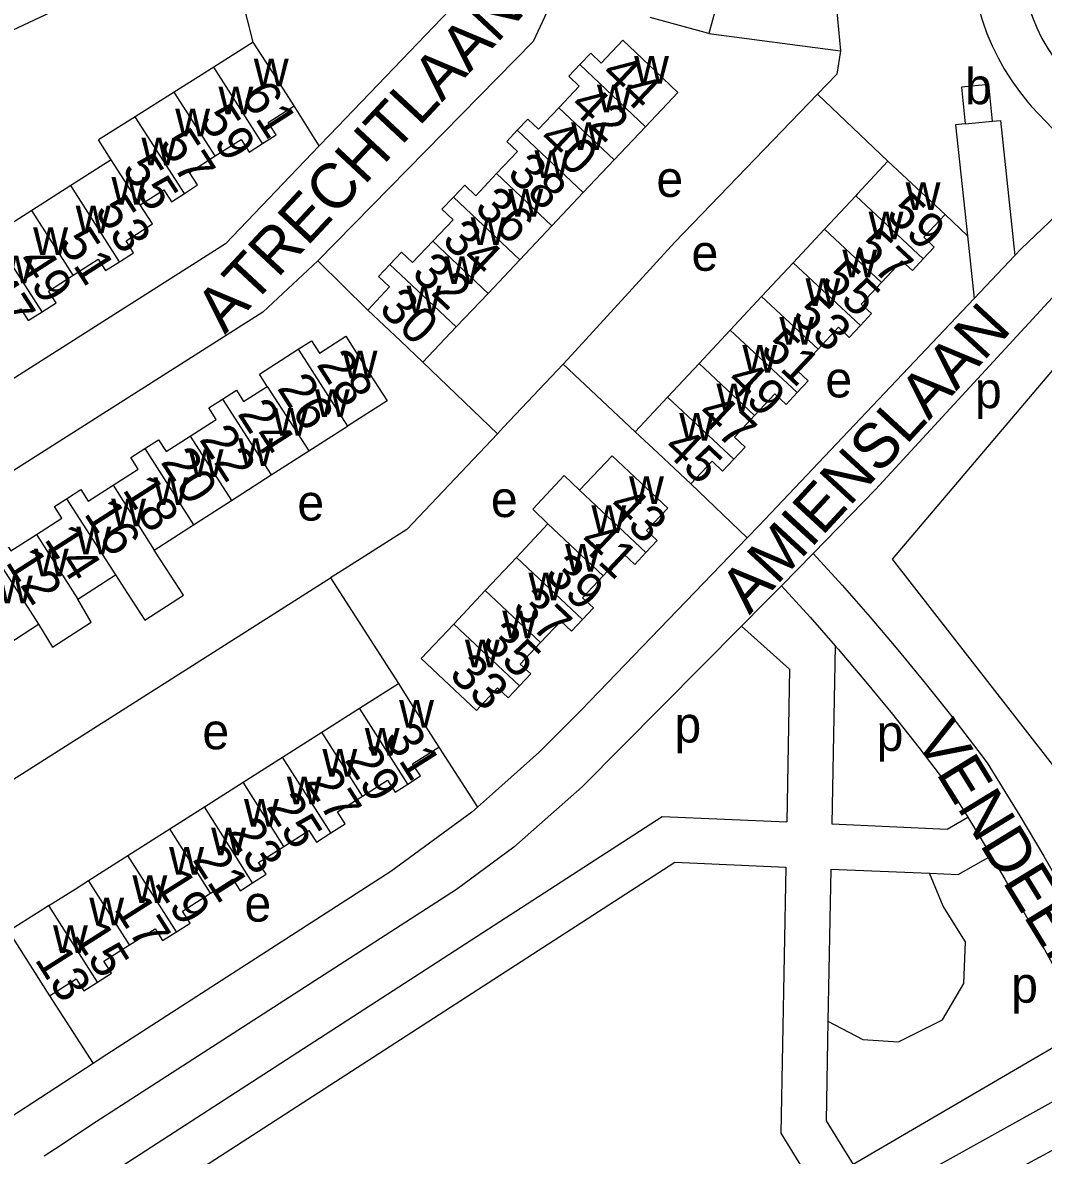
# Model space of a CAD drawing. Extents: x 157768 to 159790, y 387230 to 389604.
# Drawn here: x 159238.2 to 159351.4, y 389220.4 to 389346.2 of the extents above; entities that cross this region are included whole.
import ezdxf

# ---------------------------------------------------------------- set-up
doc = ezdxf.new("R2010")
doc.units = 0
for name, color, linetype in [('BLT_Basislijn', 7, 'Continuous'), ('BLT_Bebouwing', 7, 'Continuous'), ('BLT_Centroide', 7, 'Continuous'), ('BLT_Huisnummer', 7, 'Continuous'), ('BLT_Huisnummer_ tussenligend', 7, 'Continuous'), ('BLT_Onderverdeling_panden', 7, 'Continuous'), ('BLT_Straatnaam', 7, 'Continuous')]:
    doc.layers.add(name, color=color, linetype=linetype)

msp = doc.modelspace()

# ---------------------------------------------------------------- linework, layer by layer
at = {"layer": 'BLT_Basislijn'}
for p, q in [((159324.37, 389390.31), (159328.92, 389343.05)), ((159263.75, 389344), (159260.62, 389356.43)), ((159328.92, 389343.05), (159328.52, 389340.46)), ((159326.36, 389338.22), (159328.52, 389340.46)), ((159326.36, 389338.22), (159334.18, 389330.79)), ((159271.07, 389332.51), (159268.28, 389336.94)), ((159353.27, 389333.52), (159350.08, 389336.91)), ((159340.51, 389324.88), (159343.01, 389322.5)), ((159353.66, 389325.54), (159348.95, 389321.05)), ((159343.01, 389322.5), (159343.75, 389315.56)), ((159348.95, 389321.05), (159348.27, 389320.33)), ((159348.27, 389320.33), (159343.75, 389315.56)), ((159276.46, 389314.27), (159270.91, 389319.73)), ((159290.84, 389300.54), (159282.58, 389308.48)), ((159306.13, 389300.75), (159298.12, 389308.27)), ((159312.32, 389294.97), (159318.54, 389288.97)), ((159322.38, 389283.67), (159325.88, 389287.25)), ((159272.33, 389284.53), (159279.85, 389272.8)), ((159322.19, 389283.48), (159320.49, 389281.77)), ((159322.19, 389283.48), (159322.38, 389283.67)), ((159320.49, 389281.77), (159317.93, 389279.18)), ((159328.33, 389277.01), (159327.95, 389257.23)), ((159284.33, 389265.75), (159288.62, 389259.1)), ((159345.18, 389264), (159348.8, 389258.14)), ((159341.17, 389261.01), (159343.04, 389257.97)), ((159343.04, 389257.97), (159344.53, 389255.53)), ((159344.53, 389255.53), (159345.63, 389253.68)), ((159241.15, 389238.14), (159245.97, 389230.64)), ((159356.16, 389234.53), (159330.31, 389219.4)), ((159245.97, 389230.64), (159235.98, 389224.12))]:
    msp.add_line(p, q, dxfattribs=at)
for points in [[(159287.55, 389385.78), (159287.13, 389383.77), (159290.23, 389353.69), (159290.04, 389352.29), (159272.19, 389333.68), (159271.07, 389332.51)], [(159260.62, 389356.43), (159223.71, 389339.09), (159222.8, 389338.73)], [(159343.6, 389350.68), (159343.87, 389349.22), (159344.22, 389347.78), (159344.65, 389346.36), (159345.16, 389344.97), (159345.74, 389343.61), (159346.4, 389342.27), (159347.12, 389340.98), (159347.91, 389339.73), (159348.77, 389338.52), (159349.7, 389337.36), (159350.08, 389336.91)], [(159297.81, 389349.62), (159297.11, 389349.03), (159294.82, 389344.07), (159270.91, 389319.73)], [(159349.35, 389349.56), (159349.78, 389348), (159350.2, 389346.78), (159350.7, 389345.58), (159351.26, 389344.42), (159351.9, 389343.3), (159352.61, 389342.22), (159353.38, 389341.18), (159354.21, 389340.19), (159354.86, 389339.51)], [(159314.31, 389344.96), (159328.92, 389343.05)], [(159298.12, 389308.27), (159299.47, 389309.71), (159310.51, 389321.79), (159326.36, 389338.22)], [(159342.73, 389334.94), (159341.69, 389334.84), (159343.01, 389322.5)], [(159345.77, 389335.24), (159346.67, 389335.32), (159348.27, 389320.33)], [(159271.07, 389332.51), (159260.66, 389321.61), (159223.35, 389297.89), (159222.59, 389298.08), (159220.9, 389299.29)], [(159334.69, 389286.6), (159362.61, 389319.53), (159408.45, 389325.53)], [(159270.91, 389319.73), (159264.82, 389314.02), (159222.46, 389287.13), (159212.02, 389275.56), (159215.04, 389270.49)], [(159355.2, 389318.51), (159355.12, 389318.43), (159353.3, 389316.6), (159332.8, 389294.35), (159325.88, 389287.25)], [(159343.75, 389315.56), (159319.84, 389290.31), (159318.54, 389288.97)], [(159290.84, 389300.54), (159291.52, 389301.26), (159298.12, 389308.27)], [(159290.84, 389300.54), (159280.78, 389289.9), (159274.19, 389285.72), (159272.33, 389284.53)], [(159318.54, 389288.97), (159300.13, 389269.87), (159295.47, 389265.2), (159290.29, 389260.56), (159288.62, 389259.1)], [(159325.88, 389287.25), (159329.08, 389283.73), (159332.22, 389280.16), (159335.29, 389276.54), (159338.31, 389272.86), (159341.27, 389269.14), (159344.16, 389265.37), (159345.18, 389264)], [(159427.62, 389259.06), (159394.12, 389259.86), (159367.2, 389244.89), (159334.69, 389286.6)], [(159229.11, 389257.11), (159230.71, 389258.14), (159272.33, 389284.53)], [(159322.38, 389283.67), (159325.54, 389280.18), (159328.33, 389277.01)], [(159317.93, 389279.18), (159300.23, 389261.34), (159292.65, 389254.66), (159286.29, 389249.95), (159246.3, 389224.16), (159241.8, 389221.15), (159240.54, 389220.36)], [(159317.93, 389279.18), (159323.27, 389274.39), (159322.95, 389257.45)], [(159328.33, 389277.01), (159328.65, 389276.64), (159331.7, 389273.05), (159334.68, 389269.4), (159337.6, 389265.71), (159340.46, 389261.96), (159341.17, 389261.01)], [(159288.62, 389259.1), (159287.99, 389258.54), (159279.03, 389251.95), (159247.51, 389231.64), (159245.97, 389230.64)], [(159348.8, 389258.14), (159351.46, 389253.65), (159354.02, 389249.15), (159356.52, 389244.61), (159358.95, 389240.03), (159360.54, 389236.94)], [(159243.15, 389215.35), (159309.14, 389258.06), (159322.95, 389257.45)], [(159327.95, 389257.23), (159340.75, 389256.66), (159343.04, 389257.97)], [(159338.78, 389251.74), (159341.97, 389251.6), (159345.63, 389253.68)], [(159345.63, 389253.68), (159347.15, 389251.11), (159349.7, 389246.64), (159352.18, 389242.13), (159354.59, 389237.59), (159356.16, 389234.53)], [(159245.47, 389210.9), (159310.52, 389252.99), (159322.85, 389252.44)], [(159322.85, 389252.44), (159322.28, 389222.91), (159325.99, 389216.88)], [(159327.85, 389252.22), (159327.52, 389235.33)], [(159327.85, 389252.22), (159338.78, 389251.74)], [(159327.52, 389235.33), (159331.39, 389233.31), (159335.34, 389233.03), (159340.23, 389235.49), (159342.59, 389239.5), (159342.78, 389244.15), (159340.32, 389248.1), (159338.78, 389251.74)], [(159378.24, 389240.74), (159333.15, 389215.66), (159323.58, 389209.95), (159316.84, 389205.19), (159305.77, 389196.53), (159283.1, 389175.08), (159209.63, 389103.36), (159208.17, 389100.48), (159208.38, 389096.34), (159209.12, 389095.26), (159210.87, 389093.31)], [(159327.52, 389235.33), (159327.31, 389224.28), (159330.31, 389219.4)], [(159294.63, 389177.09), (159312.42, 389195.05), (159316.53, 389198.31), (159331.01, 389208.09), (159346.07, 389217.57), (159374.16, 389232.78)]]:
    msp.add_lwpolyline(points, dxfattribs=at)
at = {"layer": 'BLT_Bebouwing'}
for p, q in [((159263.75, 389344), (159259.36, 389341.22)), ((159259.36, 389341.22), (159254.98, 389338.46)), ((159254.98, 389338.46), (159250.66, 389335.73)), ((159250.66, 389335.73), (159246.57, 389333.15)), ((159342.73, 389334.94), (159345.77, 389335.24)), ((159307.27, 389334.61), (159303.8, 389330.94)), ((159247.97, 389330.96), (159246.57, 389333.15)), ((159247.97, 389330.96), (159243.49, 389328.09)), ((159303.8, 389330.94), (159300.37, 389327.3)), ((159340.51, 389324.88), (159334.18, 389330.79)), ((159243.49, 389328.09), (159239.18, 389325.32)), ((159300.37, 389327.3), (159296.88, 389323.62)), ((159330.6, 389326.95), (159327.14, 389323.24)), ((159239.18, 389325.32), (159234.87, 389322.56)), ((159296.88, 389323.62), (159293.31, 389319.84)), ((159327.14, 389323.24), (159323.65, 389319.52)), ((159293.31, 389319.84), (159289.8, 389316.12)), ((159323.65, 389319.52), (159320.16, 389315.77)), ((159289.8, 389316.12), (159286.27, 389312.39)), ((159320.16, 389315.77), (159316.67, 389312.04)), ((159286.27, 389312.39), (159282.58, 389308.48)), ((159316.67, 389312.04), (159313.21, 389308.33)), ((159313.21, 389308.33), (159309.72, 389304.6)), ((159309.72, 389304.6), (159306.13, 389300.75)), ((159265.75, 389295.99), (159269.91, 389298.65)), ((159257.13, 389290.43), (159261.33, 389293.13)), ((159252.75, 389287.62), (159257.13, 389290.43)), ((159296.44, 389290.53), (159292.94, 389286.8)), ((159292.94, 389286.8), (159289.48, 389283.13)), ((159244.27, 389282.18), (159248.46, 389284.86)), ((159289.48, 389283.13), (159285.99, 389279.41)), ((159235.63, 389276.64), (159239.92, 389279.39)), ((159275.54, 389270.06), (159279.85, 389272.8)), ((159271.36, 389267.4), (159275.54, 389270.06)), ((159266.99, 389264.63), (159271.36, 389267.4)), ((159262.61, 389261.85), (159266.99, 389264.63)), ((159258.32, 389259.12), (159262.61, 389261.85)), ((159254.48, 389256.68), (159258.32, 389259.12)), ((159249.83, 389253.72), (159254.48, 389256.68)), ((159245.46, 389250.95), (159249.83, 389253.72)), ((159236.59, 389245.31), (159241.15, 389238.14))]:
    msp.add_line(p, q, dxfattribs=at)
for points in [[(159316.65, 389355.57), (159317.49, 389347.28), (159315.12, 389347.92), (159314.31, 389344.96)], [(159314.31, 389344.96), (159307.79, 389346.74)], [(159268.28, 389336.94), (159265.58, 389341.15), (159263.75, 389344)], [(159299.98, 389341.51), (159301.19, 389342.79), (159302.36, 389341.69), (159304.74, 389344.21), (159308.37, 389340.77), (159310.87, 389338.42), (159307.27, 389334.61)], [(159297.67, 389336.73), (159299.93, 389339.13), (159298.77, 389340.23), (159299.98, 389341.51)], [(159345.77, 389335.24), (159345.38, 389339.31), (159342.34, 389339.02), (159342.73, 389334.94)], [(159264.78, 389332.76), (159266.28, 389333.72), (159265.4, 389335.09), (159268.28, 389336.94)], [(159293.05, 389334.22), (159294.22, 389335.46), (159295.4, 389334.34), (159297.67, 389336.73)], [(159290.75, 389329.41), (159293.07, 389331.85), (159291.87, 389332.98), (159293.05, 389334.22)], [(159259.53, 389331.37), (159262.39, 389333.2), (159263.29, 389331.8), (159264.78, 389332.76)], [(159256.12, 389327.22), (159257.57, 389328.15), (159256.68, 389329.54), (159259.53, 389331.37)], [(159334.18, 389330.79), (159330.77, 389327.14), (159330.6, 389326.95)], [(159285.95, 389326.79), (159287.21, 389328.12), (159288.44, 389326.96), (159290.75, 389329.41)], [(159251.2, 389325.93), (159253.82, 389327.61), (159254.67, 389326.29), (159256.12, 389327.22)], [(159283.67, 389321.91), (159285.92, 389324.29), (159284.69, 389325.46), (159285.95, 389326.79)], [(159248.92, 389319.63), (159250.47, 389320.63), (159249.63, 389321.94), (159252.55, 389323.82), (159251.2, 389325.93)], [(159338.1, 389319.94), (159339.32, 389321.24), (159338.14, 389322.34), (159340.51, 389324.88)], [(159278.92, 389319.34), (159280.2, 389320.69), (159281.42, 389319.53), (159283.67, 389321.91)], [(159243.78, 389318.15), (159246.55, 389319.92), (159247.37, 389318.64), (159248.92, 389319.63)], [(159338.1, 389319.94), (159336.89, 389318.64), (159335.72, 389319.73), (159333.47, 389317.33)], [(159276.46, 389314.27), (159278.87, 389316.83), (159277.65, 389317.99), (159278.92, 389319.34)], [(159240.32, 389314.07), (159241.86, 389315.06), (159241.02, 389316.37), (159243.78, 389318.15)], [(159333.47, 389317.33), (159331.22, 389314.92), (159332.35, 389313.87), (159331.12, 389312.55)], [(159235.22, 389312.65), (159237.94, 389314.39), (159238.78, 389313.09), (159240.32, 389314.07)], [(159282.58, 389308.48), (159280.09, 389310.84), (159276.46, 389314.27)], [(159331.12, 389312.55), (159329.88, 389311.23), (159328.68, 389312.35), (159326.42, 389309.93)], [(159268.74, 389309.92), (159270.22, 389310.86), (159271.11, 389309.49), (159274.01, 389311.35), (159276.7, 389307.14), (159278.59, 389304.2), (159274.21, 389301.39)], [(159265.3, 389305.79), (159264.44, 389307.16), (159268.74, 389309.92)], [(159326.42, 389309.93), (159324.15, 389307.51), (159325.32, 389306.41), (159324.1, 389305.1)], [(159260.35, 389304.39), (159261.88, 389305.36), (159262.68, 389304.11), (159265.3, 389305.79)], [(159324.1, 389305.1), (159322.87, 389303.79), (159321.62, 389304.96), (159319.38, 389302.56)], [(159256.74, 389300.27), (159259.65, 389302.13), (159258.83, 389303.41), (159260.35, 389304.39)], [(159319.38, 389302.56), (159317.14, 389300.17), (159318.33, 389299.06), (159317.08, 389297.72)], [(159269.91, 389298.65), (159274.21, 389301.39)], [(159251.7, 389298.89), (159253.24, 389299.87), (159254.08, 389298.56), (159256.74, 389300.27)], [(159306.13, 389300.75), (159308.67, 389298.39), (159312.32, 389294.97)], [(159248.21, 389294.84), (159250.99, 389296.62), (159250.17, 389297.9), (159251.7, 389298.89)], [(159307.32, 389287.36), (159308.56, 389288.67), (159307.39, 389289.78), (159309.75, 389292.29), (159306.1, 389295.71), (159303.56, 389298.1), (159299.96, 389294.28)], [(159317.08, 389297.72), (159315.83, 389296.39), (159314.66, 389297.48), (159312.32, 389294.97)], [(159261.33, 389293.13), (159265.75, 389295.99)], [(159299.96, 389294.28), (159298.26, 389295.9), (159294.77, 389292.18), (159296.44, 389290.53)], [(159243.03, 389293.31), (159244.62, 389294.33), (159245.43, 389293.06), (159248.21, 389294.84)], [(159239.68, 389289.34), (159242.51, 389291.15), (159241.68, 389292.45), (159243.03, 389293.31)], [(159234.49, 389287.85), (159236.02, 389288.83), (159236.86, 389287.53), (159239.68, 389289.34)], [(159248.46, 389284.86), (159249.79, 389282.8), (159251.73, 389279.83), (159256.01, 389282.61), (159254.09, 389285.56), (159252.75, 389287.62)], [(159307.32, 389287.36), (159306.09, 389286.04), (159304.85, 389287.2), (159302.56, 389284.77)], [(159302.56, 389284.77), (159300.28, 389282.34), (159301.49, 389281.2), (159300.27, 389279.91)], [(159239.92, 389279.39), (159241.47, 389276.86), (159245.76, 389279.62), (159244.27, 389282.18)], [(159300.27, 389279.91), (159299.06, 389278.62), (159297.87, 389279.73), (159295.63, 389277.35)], [(159285.99, 389279.41), (159282.39, 389275.58), (159284.86, 389273.25), (159288.51, 389269.83), (159290.85, 389272.32), (159292.04, 389271.21), (159293.29, 389272.54)], [(159295.63, 389277.35), (159293.38, 389274.96), (159294.54, 389273.87), (159293.29, 389272.54)], [(159279.85, 389272.8), (159281.65, 389269.97), (159284.33, 389265.75)], [(159280.89, 389261.65), (159282.3, 389262.55), (159281.43, 389263.91), (159284.33, 389265.75)], [(159275.86, 389260.31), (159278.64, 389262.07), (159279.48, 389260.75), (159280.89, 389261.65)], [(159272.34, 389256.22), (159273.93, 389257.22), (159273.09, 389258.55), (159275.86, 389260.31)], [(159267.13, 389254.73), (159269.93, 389256.51), (159270.76, 389255.21), (159272.34, 389256.22)], [(159263.68, 389250.69), (159265.17, 389251.63), (159264.33, 389252.95), (159267.13, 389254.73)], [(159241.08, 389248.17), (159243.97, 389250), (159245.46, 389250.95)], [(159259.02, 389249.53), (159259.75, 389250), (159261.48, 389251.1), (159262.18, 389250), (159262.3, 389249.81), (159262.6, 389250), (159263.68, 389250.69)], [(159255.22, 389245.24), (159256.74, 389246.21), (159255.89, 389247.55), (159259.02, 389249.53)], [(159241.08, 389248.17), (159240.81, 389247.99), (159236.59, 389245.31)], [(159250.01, 389243.79), (159252.85, 389245.59), (159253.69, 389244.27), (159255.22, 389245.24)], [(159246.48, 389239.66), (159248.02, 389240.64), (159247.17, 389241.98), (159250.01, 389243.79)], [(159241.15, 389238.14), (159244.09, 389240.01), (159244.93, 389238.68), (159246.48, 389239.66)]]:
    msp.add_lwpolyline(points, dxfattribs=at)
at = {"layer": 'BLT_Onderverdeling_panden'}
for p, q in [((159264.78, 389332.76), (159259.36, 389341.22)), ((159299.98, 389341.51), (159307.27, 389334.61)), ((159259.53, 389331.37), (159254.98, 389338.46)), ((159297.67, 389336.73), (159303.8, 389330.94)), ((159256.12, 389327.22), (159250.66, 389335.73)), ((159293.05, 389334.22), (159300.37, 389327.3)), ((159251.2, 389325.93), (159247.97, 389330.96)), ((159290.75, 389329.41), (159296.88, 389323.62)), ((159248.92, 389319.63), (159243.49, 389328.09)), ((159285.95, 389326.79), (159293.31, 389319.84)), ((159338.1, 389319.94), (159330.6, 389326.95)), ((159243.78, 389318.15), (159239.18, 389325.32)), ((159240.32, 389314.07), (159234.87, 389322.56)), ((159333.47, 389317.33), (159327.14, 389323.24)), ((159283.67, 389321.91), (159289.8, 389316.12)), ((159278.92, 389319.34), (159286.27, 389312.39)), ((159331.12, 389312.55), (159323.65, 389319.52)), ((159326.42, 389309.93), (159320.16, 389315.77)), ((159324.1, 389305.1), (159316.67, 389312.04)), ((159268.74, 389309.92), (159274.21, 389301.39)), ((159319.38, 389302.56), (159313.21, 389308.33)), ((159265.3, 389305.79), (159269.91, 389298.65)), ((159260.35, 389304.39), (159265.75, 389295.99)), ((159317.08, 389297.72), (159309.72, 389304.6)), ((159256.74, 389300.27), (159261.33, 389293.13)), ((159251.7, 389298.89), (159257.13, 389290.43)), ((159248.21, 389294.84), (159252.75, 389287.62)), ((159307.32, 389287.36), (159299.96, 389294.28)), ((159243.03, 389293.31), (159248.46, 389284.86)), ((159302.56, 389284.77), (159296.44, 389290.53)), ((159239.68, 389289.34), (159244.27, 389282.18)), ((159234.49, 389287.85), (159239.92, 389279.39)), ((159300.27, 389279.91), (159292.94, 389286.8)), ((159295.63, 389277.35), (159289.48, 389283.13)), ((159293.29, 389272.54), (159285.99, 389279.41)), ((159280.89, 389261.65), (159275.54, 389270.06)), ((159275.86, 389260.31), (159271.36, 389267.4)), ((159272.34, 389256.22), (159266.99, 389264.63)), ((159267.13, 389254.73), (159262.61, 389261.85)), ((159263.68, 389250.69), (159258.32, 389259.12)), ((159259.02, 389249.53), (159254.48, 389256.68)), ((159255.22, 389245.24), (159249.83, 389253.72)), ((159250.01, 389243.79), (159245.46, 389250.95)), ((159246.48, 389239.66), (159241.08, 389248.17))]:
    msp.add_line(p, q, dxfattribs=at)

# ---------------------------------------------------------------- texts
at = {"layer": 'BLT_Centroide'}
for s, p in [('w', (159306.01, 389339.41)), ('w', (159263.81, 389339.09)), ('b', (159342.73, 389337.12)), ('w', (159259.89, 389336)), ('w', (159301.89, 389336.22)), ('w', (159255.09, 389333.55)), ('w', (159299.02, 389332.03)), ('w', (159251.34, 389330.34)), ('w', (159294.96, 389328.91)), ('e', (159308.48, 389326.83)), ('w', (159248.02, 389325.95)), ('w', (159292.04, 389324.62)), ('w', (159336.14, 389325.38)), ('w', (159244.05, 389322.77)), ('w', (159332.03, 389322.12)), ('w', (159287.88, 389321.47)), ('w', (159239.33, 389320.36)), ('e', (159312.38, 389318.63)), ('w', (159235.47, 389317.22)), ('w', (159284.98, 389317.16)), ('w', (159329.12, 389317.91)), ('w', (159325.03, 389314.72)), ('w', (159280.76, 389313.91)), ('w', (159322.13, 389310.44)), ('w', (159273.67, 389306.69)), ('w', (159318.03, 389307.31)), ('e', (159327.23, 389304.57)), ('w', (159315.15, 389303.03)), ('p', (159343.83, 389303.38)), ('w', (159270.59, 389302.41)), ('w', (159265.95, 389300.33)), ('w', (159311.02, 389299.78)), ('w', (159262.09, 389296.94)), ('w', (159256.58, 389295.72)), ('w', (159252.67, 389292.64)), ('w', (159305.45, 389292.72)), ('w', (159247.98, 389290.27)), ('e', (159268.64, 389290.9)), ('e', (159290.12, 389291.29)), ('w', (159301.27, 389289.53)), ('w', (159244.12, 389287.14)), ('w', (159239.39, 389284.69)), ('w', (159298.36, 389285.22)), ('w', (159235.41, 389281.72)), ('w', (159294.28, 389282.06)), ('w', (159291.38, 389277.84)), ('w', (159287.24, 389274.62)), ('w', (159279.94, 389267.91)), ('e', (159258.1, 389265.51)), ('p', (159310.48, 389266.26)), ('p', (159332.92, 389265.33)), ('w', (159276.12, 389264.81)), ('w', (159271.42, 389262.47)), ('w', (159267.47, 389259.41)), ('w', (159262.72, 389256.92)), ('w', (159259.08, 389253.73)), ('w', (159254.42, 389251.58)), ('w', (159250.34, 389248.45)), ('e', (159262.77, 389246.38)), ('w', (159245.55, 389245.97)), ('w', (159241.53, 389242.91)), ('p', (159347.85, 389237.38))]:
    msp.add_text(s, height=4, dxfattribs=at).set_placement(p)
at = {"layer": 'BLT_Huisnummer'}
for s, rotation, p in [('44', 316.6177, (159302.14, 389340.27)), ('61', 302.6698, (159262.28, 389338.04)), ('55', 302.6698, (159249.11, 389329.96)), ('38', 316.6177, (159291.78, 389329.22)), ('59', 316.9532, (159333.82, 389324.72)), ('51', 302.6698, (159242.07, 389321.76)), ('34', 316.6177, (159284.54, 389321.83)), ('47', 302.6698, (159233.21, 389316.86)), ('30', 316.6177, (159277.55, 389314.23)), ('53', 316.9532, (159323.38, 389313.47)), ('28', 302.6864, (159270.69, 389308.23)), ('49', 316.9532, (159316.09, 389306.21)), ('22', 302.6864, (159257.68, 389299.92)), ('45', 316.9532, (159309.08, 389298.74)), ('18', 302.6864, (159249.16, 389294.33)), ('43', 316.7666, (159302.94, 389292.21)), ('14', 302.6864, (159240.48, 389288.84)), ('37', 316.7666, (159292.34, 389281.05)), ('33', 316.7666, (159285.34, 389273.64)), ('31', 302.4304, (159278.2, 389266.8)), ('25', 302.4304, (159265.09, 389259.14)), ('21', 302.4304, (159256.93, 389253.29)), ('17', 302.4304, (159248.21, 389247.85)), ('13', 302.4304, (159239.42, 389242.18))]:
    msp.add_text(s, height=4, rotation=rotation, dxfattribs=at).set_placement(p)
at = {"layer": 'BLT_Huisnummer_ tussenligend'}
for s, rotation, p in [('42', 316.6177, (159298.7, 389336.77)), ('59', 302.6698, (159257.67, 389335.47)), ('57', 302.6698, (159253.19, 389332.73)), ('40', 316.6177, (159295.23, 389333)), ('36', 316.6177, (159288.15, 389325.44)), ('53', 302.6698, (159246.07, 389325.29)), ('57', 316.9532, (159330.21, 389320.79)), ('49', 302.6698, (159237.37, 389319.68)), ('32', 316.6177, (159281.18, 389318.15)), ('55', 316.9532, (159326.6, 389317.33)), ('51', 316.9532, (159319.88, 389309.68)), ('26', 302.6864, (159266.32, 389305.6)), ('24', 302.6864, (159261.92, 389302.77)), ('47', 316.9532, (159312.84, 389302.53)), ('20', 302.6864, (159253.4, 389297.41)), ('16', 302.6864, (159244.88, 389291.67)), ('41', 316.7666, (159299.68, 389288.28)), ('12', 302.6864, (159236.19, 389286.27)), ('39', 316.7666, (159295.96, 389284.74)), ('35', 316.7666, (159288.95, 389277.25)), ('29', 302.4304, (159273.81, 389264.34)), ('27', 302.4304, (159269.41, 389261.91)), ('23', 302.4304, (159260.78, 389256.34)), ('19', 302.4304, (159252.69, 389250.67)), ('15', 302.4304, (159243.66, 389244.85))]:
    msp.add_text(s, height=4, rotation=rotation, dxfattribs=at).set_placement(p)
at = {"layer": 'BLT_Straatnaam'}
for s, rotation, p in [('ATRECHTLAAN', 46.9799, (159260.6, 389311.48)), ('AMIENSLAAN', 47.3058, (159318.81, 389280.37)), ('VENDEEPAD', 301.4653, (159337.12, 389266.68))]:
    msp.add_text(s, height=5, rotation=rotation, dxfattribs=at).set_placement(p)

doc.saveas('drawing.dxf')
